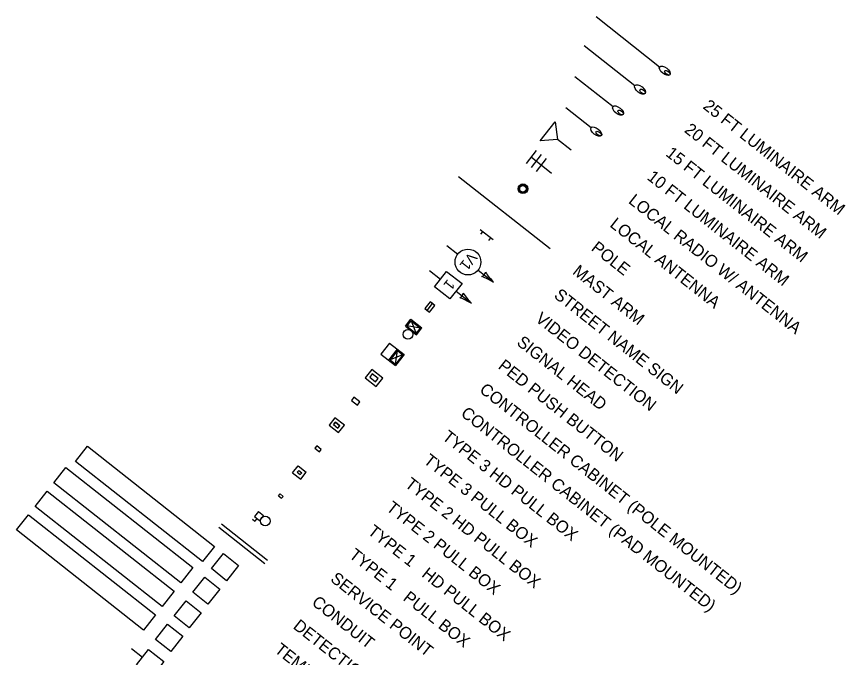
# Model space of a CAD drawing. Extents: x 999004 to 1000413, y 1985693 to 1986834.
# Drawn here: x 1000156.9 to 1000413.2, y 1986635.7 to 1986833.7 of the extents above; entities that cross this region are included whole.
import ezdxf

# ---------------------------------------------------------------- set-up
doc = ezdxf.new("R2010")
doc.units = 0
for name, color, linetype in [('_CIVIL_CONSTRUCTION', 7, 'Continuous'), ('DSN_ROW_Line-Annotation', 7, 'Continuous'), ('S_CROSS_DRAIN', 7, 'Continuous'), ('S_CURB', 7, 'Continuous'), ('S_DRIVEWAY', 7, 'Continuous'), ('S_EDGE_PAVEMENT', 7, 'Continuous'), ('S_HWY_SYMBOLS', 7, 'Continuous'), ('S_HWY_TEXT', 7, 'Continuous'), ('S_PARKING', 7, 'Continuous'), ('S_PAVEMENT_CROWN', 7, 'Continuous'), ('S_SIDE_DRAIN', 7, 'Continuous'), ('S_SIDEWALK', 7, 'Continuous'), ('S_WALL', 7, 'Continuous'), ('S_WALL_ANNOT', 7, 'Continuous')]:
    doc.layers.add(name, color=color, linetype=linetype)

msp = doc.modelspace()

# ---------------------------------------------------------------- linework, layer by layer
at = {"layer": '_CIVIL_CONSTRUCTION'}
for p, q in [((1000156.94, 1986675.09), (1000160.65, 1986679.8)), ((1000160.65, 1986679.8), (1000199.92, 1986648.85)), ((1000196.21, 1986644.13), (1000156.94, 1986675.09)), ((1000199.92, 1986648.85), (1000196.21, 1986644.13))]:
    msp.add_line(p, q, dxfattribs=at)
msp.add_lwpolyline([(1000204.59, 1986637.53), (1000199.88, 1986641.24), (1000203.59, 1986645.95), (1000208.3, 1986642.24)], close=True, dxfattribs=at)
at = {"layer": 'DSN_ROW_Line-Annotation'}
msp.add_line((1000192.45, 1986638.47), (1000195.87, 1986635.78), dxfattribs=at)
msp.add_lwpolyline([(1000194, 1986633.41), (1000197.75, 1986638.18), (1000202.52, 1986634.42), (1000198.76, 1986629.66)], close=True, dxfattribs=at)
at = {"layer": 'S_CROSS_DRAIN'}
msp.add_lwpolyline([(1000284.84, 1986745.55), (1000283.21, 1986743.48), (1000283.9, 1986742.94), (1000285.53, 1986745.01)], close=True, dxfattribs=at)
at = {"layer": 'S_CURB'}
for p, q in [((1000272.28, 1986732.85), (1000269.6, 1986729.45)), ((1000274.64, 1986730.99), (1000271.96, 1986727.59)), ((1000272.28, 1986732.85), (1000276.79, 1986729.29)), ((1000269.6, 1986729.45), (1000274.11, 1986725.89)), ((1000274.69, 1986730.53), (1000272.42, 1986727.64)), ((1000276.31, 1986729.22), (1000272.42, 1986727.64)), ((1000274.05, 1986726.36), (1000274.69, 1986730.53)), ((1000276.33, 1986729.24), (1000274.05, 1986726.36)), ((1000276.79, 1986729.29), (1000274.11, 1986725.89)), ((1000274.69, 1986730.53), (1000276.33, 1986729.24)), ((1000272.42, 1986727.64), (1000274.05, 1986726.36))]:
    msp.add_line(p, q, dxfattribs=at)
at = {"layer": 'S_DRIVEWAY'}
for p, q in [((1000231.7, 1986680.79), (1000230.46, 1986679.22)), ((1000231.7, 1986680.79), (1000233.27, 1986679.55)), ((1000233.27, 1986679.55), (1000232.03, 1986677.98)), ((1000220.31, 1986676.96), (1000234.55, 1986665.73)), ((1000229.84, 1986678.43), (1000230.62, 1986677.82)), ((1000230.46, 1986679.22), (1000232.03, 1986677.98)), ((1000231.24, 1986678.6), (1000230.62, 1986677.82)), ((1000219.49, 1986675.91), (1000233.73, 1986664.69))]:
    msp.add_line(p, q, dxfattribs=at)
msp.add_circle((1000233.82, 1986677.84), 1.5, dxfattribs=at)
at = {"layer": 'S_EDGE_PAVEMENT'}
msp.add_line((1000293.6, 1986784.34), (1000321.87, 1986762.05), dxfattribs=at)
for radius in [1.5, 1.25, 1]:
    msp.add_circle((1000313.5, 1986780.5), radius, dxfattribs=at)
at = {"layer": 'S_HWY_SYMBOLS'}
for p, q in [((1000162.7, 1986682.39), (1000166.42, 1986687.1)), ((1000166.42, 1986687.1), (1000205.68, 1986656.15)), ((1000201.97, 1986651.44), (1000162.7, 1986682.39)), ((1000205.68, 1986656.15), (1000201.97, 1986651.44))]:
    msp.add_line(p, q, dxfattribs=at)
msp.add_lwpolyline([(1000210.35, 1986644.83), (1000205.64, 1986648.54), (1000209.35, 1986653.25), (1000214.06, 1986649.54)], close=True, dxfattribs=at)
at = {"layer": 'S_HWY_TEXT'}
for p, q in [((1000168.46, 1986689.69), (1000172.18, 1986694.4)), ((1000172.18, 1986694.4), (1000211.44, 1986663.45)), ((1000207.73, 1986658.74), (1000168.46, 1986689.69)), ((1000211.44, 1986663.45), (1000207.73, 1986658.74))]:
    msp.add_line(p, q, dxfattribs=at)
msp.add_lwpolyline([(1000216.11, 1986652.13), (1000211.4, 1986655.84), (1000215.11, 1986660.56), (1000219.83, 1986656.84)], close=True, dxfattribs=at)
at = {"layer": 'S_PARKING'}
for p, q in [((1000175.13, 1986696.28), (1000178.84, 1986700.99)), ((1000178.84, 1986700.99), (1000218.11, 1986670.03)), ((1000214.4, 1986665.32), (1000175.13, 1986696.28)), ((1000218.11, 1986670.03), (1000214.4, 1986665.32))]:
    msp.add_line(p, q, dxfattribs=at)
msp.add_lwpolyline([(1000221.87, 1986659.43), (1000217.16, 1986663.14), (1000220.87, 1986667.86), (1000225.59, 1986664.14)], close=True, dxfattribs=at)
at = {"layer": 'S_PAVEMENT_CROWN'}
for p, q in [((1000289.97, 1986763.02), (1000293.37, 1986760.34)), ((1000284.62, 1986755.29), (1000288.04, 1986752.6)), ((1000299.65, 1986755.39), (1000304.41, 1986751.64)), ((1000292.81, 1986748.87), (1000297.56, 1986745.13))]:
    msp.add_line(p, q, dxfattribs=at)
msp.add_lwpolyline([(1000286.17, 1986750.23), (1000289.92, 1986754.99), (1000294.68, 1986751.24), (1000290.93, 1986746.48)], close=True, dxfattribs=at)
msp.add_circle((1000296.51, 1986757.87), 4, dxfattribs=at)
for centre, radius, start, end in [((1000300.28, 1986754.9), 1.63, 289.9043, 353.599), ((1000325.92, 1986771.79), 29.47, 215.4052, 223.1433), ((1000289.84, 1986726.02), 29.47, 60.36, 68.0981), ((1000293.42, 1986748.39), 1.63, 289.9043, 353.599), ((1000282.98, 1986719.51), 29.47, 60.36, 68.0981), ((1000319.06, 1986765.28), 29.47, 215.4052, 223.1433)]:
    msp.add_arc(centre, radius, start, end, dxfattribs=at)
at = {"layer": 'S_SIDE_DRAIN'}
for p, q in [((1000304.25, 1986764.74), (1000300.32, 1986767.83)), ((1000300.49, 1986766.43), (1000301.11, 1986767.21)), ((1000303.47, 1986765.35), (1000302.85, 1986764.57)), ((1000304.25, 1986764.74), (1000303.47, 1986765.35))]:
    msp.add_line(p, q, dxfattribs=at)
at = {"layer": 'S_SIDEWALK'}
for p, q in [((1000266.75, 1986724.69), (1000264.72, 1986722.12)), ((1000266.91, 1986723.29), (1000266.13, 1986722.29)), ((1000270.15, 1986722.01), (1000266.75, 1986724.69)), ((1000268.75, 1986721.84), (1000266.91, 1986723.29)), ((1000264.72, 1986722.12), (1000268.12, 1986719.44)), ((1000266.13, 1986722.29), (1000267.96, 1986720.84)), ((1000267.96, 1986720.84), (1000268.75, 1986721.84)), ((1000268.12, 1986719.44), (1000270.15, 1986722.01)), ((1000261.26, 1986716.13), (1000260.47, 1986715.13)), ((1000263.09, 1986714.68), (1000261.26, 1986716.13)), ((1000260.47, 1986715.13), (1000262.3, 1986713.68)), ((1000262.3, 1986713.68), (1000263.09, 1986714.68)), ((1000255.35, 1986709.77), (1000253.54, 1986707.48)), ((1000254.94, 1986707.64), (1000255.51, 1986708.37)), ((1000255.51, 1986708.37), (1000254.94, 1986707.64)), ((1000254.94, 1986707.64), (1000256.32, 1986706.56)), ((1000254.94, 1986707.64), (1000256.32, 1986706.56)), ((1000258.29, 1986707.45), (1000255.35, 1986709.77)), ((1000255.51, 1986708.37), (1000256.89, 1986707.28)), ((1000256.89, 1986707.28), (1000255.51, 1986708.37)), ((1000253.54, 1986707.48), (1000256.48, 1986705.16)), ((1000256.32, 1986706.56), (1000256.89, 1986707.28)), ((1000256.32, 1986706.56), (1000256.89, 1986707.28)), ((1000256.48, 1986705.16), (1000258.29, 1986707.45)), ((1000249.76, 1986701.06), (1000249.19, 1986700.34)), ((1000249.19, 1986700.34), (1000250.56, 1986699.26)), ((1000251.13, 1986699.98), (1000249.76, 1986701.06)), ((1000250.56, 1986699.26), (1000251.13, 1986699.98))]:
    msp.add_line(p, q, dxfattribs=at)
msp.add_lwpolyline([(1000283.21, 1986743.48), (1000284.58, 1986742.4), (1000286.21, 1986744.47), (1000284.84, 1986745.55)], close=True, dxfattribs=at)
at = {"layer": 'S_WALL'}
for p, q in [((1000336.14, 1986833.69), (1000355.77, 1986818.22)), ((1000332.42, 1986824.78), (1000348.13, 1986812.4)), ((1000329.57, 1986815.19), (1000341.35, 1986805.9)), ((1000326.74, 1986805.58), (1000334.59, 1986799.39)), ((1000318.78, 1986795.28), (1000323.42, 1986801.17)), ((1000323.42, 1986801.17), (1000324.24, 1986795.75)), ((1000324.24, 1986795.75), (1000318.78, 1986795.28)), ((1000328.44, 1986792.44), (1000324.24, 1986795.75)), ((1000317.59, 1986792.28), (1000314.5, 1986788.36)), ((1000316.04, 1986790.32), (1000322.33, 1986785.37)), ((1000319.16, 1986791.04), (1000316.07, 1986787.12)), ((1000320.73, 1986789.81), (1000317.64, 1986785.88)), ((1000277.17, 1986738.05), (1000278.87, 1986740.2)), ((1000277.64, 1986738.1), (1000278.93, 1986739.74)), ((1000278.87, 1986740.2), (1000282.27, 1986737.52)), ((1000278.93, 1986739.74), (1000281.81, 1986737.47)), ((1000278.94, 1986739.72), (1000280.52, 1986735.83)), ((1000277.17, 1986738.05), (1000280.58, 1986735.37)), ((1000281.81, 1986737.47), (1000277.64, 1986738.11)), ((1000277.64, 1986738.1), (1000280.52, 1986735.83)), ((1000280.52, 1986735.83), (1000281.81, 1986737.47)), ((1000280.58, 1986735.37), (1000282.27, 1986737.52)), ((1000242.3, 1986692.77), (1000243.99, 1986694.91)), ((1000243.99, 1986694.91), (1000246.5, 1986692.94)), ((1000242.3, 1986692.77), (1000244.81, 1986690.8)), ((1000243.71, 1986692.94), (1000244.16, 1986693.51)), ((1000243.71, 1986692.94), (1000244.64, 1986692.2)), ((1000244.16, 1986693.51), (1000245.09, 1986692.77)), ((1000244.64, 1986692.2), (1000245.09, 1986692.77)), ((1000244.81, 1986690.8), (1000246.5, 1986692.94)), ((1000237.95, 1986685.64), (1000238.4, 1986686.21)), ((1000237.95, 1986685.64), (1000238.88, 1986684.9)), ((1000238.4, 1986686.21), (1000239.34, 1986685.47)), ((1000238.88, 1986684.9), (1000239.34, 1986685.47))]:
    msp.add_line(p, q, dxfattribs=at)
msp.add_circle((1000277.95, 1986735.53), 1.5, dxfattribs=at)
for centre, major_axis in [((1000357.35, 1986816.98), (1.57, -1.24)), ((1000358.13, 1986816.36), (-0.785, 0.619)), ((1000349.7, 1986811.16), (1.57, -1.24)), ((1000350.49, 1986810.54), (-0.785, 0.619)), ((1000342.92, 1986804.66), (1.57, -1.24)), ((1000343.71, 1986804.04), (-0.785, 0.619)), ((1000336.16, 1986798.15), (1.57, -1.24)), ((1000336.95, 1986797.53), (-0.785, 0.619))]:
    msp.add_ellipse(centre, major_axis=major_axis, ratio=0.5, dxfattribs=at)

# ---------------------------------------------------------------- texts
at = {"layer": 'S_PAVEMENT_CROWN'}
for s, p in [('V1', (1000297.04, 1986761.12)), ('1', (1000290.25, 1986752.74))]:
    msp.add_text(s, height=3.25, rotation=231.7516, dxfattribs=at).set_placement(p)
at = {"layer": 'S_WALL_ANNOT'}
for s, p in [('25 FT LUMINAIRE ARM', (1000368.91, 1986805.51)), ('20 FT LUMINAIRE ARM', (1000363.15, 1986798.21)), ('15 FT LUMINAIRE ARM', (1000357.39, 1986790.91)), ('10 FT LUMINAIRE ARM', (1000351.63, 1986783.6)), ('LOCAL RADIO W/ ANTENNA', (1000345.87, 1986776.3)), ('LOCAL ANTENNA', (1000340.11, 1986769)), ('POLE', (1000334.35, 1986761.7)), ('MAST ARM', (1000328.59, 1986754.4)), ('STREET NAME SIGN', (1000322.83, 1986747.1)), ('VIDEO DETECTION', (1000317.07, 1986739.8)), ('SIGNAL HEAD', (1000311.31, 1986732.5)), ('PED PUSH BUTTON', (1000305.55, 1986725.2)), ('CONTROLLER CABINET (POLE MOUNTED)', (1000299.79, 1986717.9)), ('CONTROLLER CABINET (PAD MOUNTED)', (1000294.03, 1986710.59)), ('TYPE 3 HD PULL BOX', (1000288.27, 1986703.29)), ('TYPE 3 PULL BOX', (1000282.51, 1986695.99)), ('TYPE 2 HD PULL BOX', (1000276.74, 1986688.69)), ('TYPE 2 PULL BOX', (1000270.98, 1986681.39)), ('TYPE 1   HD PULL BOX', (1000265.22, 1986674.09)), ('TYPE 1   PULL BOX', (1000259.46, 1986666.79)), ('SERVICE POINT', (1000253.7, 1986659.49)), ('CONDUIT', (1000247.94, 1986652.19)), ('DETECTION ZONE', (1000242.18, 1986644.88)), ('TEMP DETECTION ZONE STAGE 1', (1000236.42, 1986637.58))]:
    msp.add_text(s, height=3.72, rotation=321.7265, dxfattribs=at).set_placement(p)

doc.saveas('drawing.dxf')
